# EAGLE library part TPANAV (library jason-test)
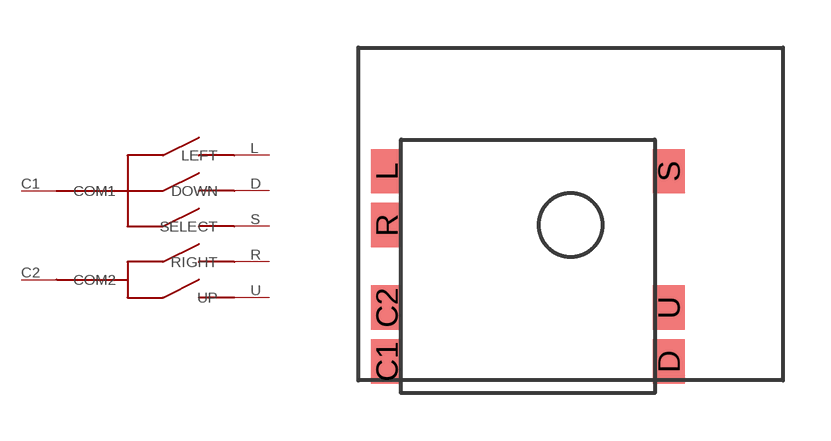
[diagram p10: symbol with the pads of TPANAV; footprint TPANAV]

Designator prefix -

## TPANAV  [TPANAV]
C1  COM1
C2  COM2
D  DOWN
L  LEFT
R  RIGHT
S  SELECT
U  UP

## Footprint TPANAV (pad centres in mm)
smd 1 x 1.4: C1 -5.8,-4.3; C2 -5.8,-2.6; D 3.1,-4.3; L -5.8,1.7; R -5.8,0; S 3.1,1.7; U 3.1,-2.6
